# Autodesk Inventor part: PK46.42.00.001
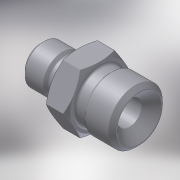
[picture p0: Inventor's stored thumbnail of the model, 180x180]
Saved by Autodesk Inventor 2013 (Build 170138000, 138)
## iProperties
Created: 2005-06
Part Number: PK46.42.00.001
Material: Steel, Mild
Document SubType Name: Modeling
Designer: salex
Manufacturer: Standard
Standards Organization: Custom
Density: 7.86 g/cm^3
Mass: 73.9851 g
Surface Area: 45.5262 cm^2
Volume: 9.41287 cm^3
Author: salex
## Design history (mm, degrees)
sketch "Эскиз1"
  geometry: L1 (0, 0)-(44.165, 0); L2 (0, 5)-(0, 8); L3 (0, 8)-(8.9, 8); L4 (8.9, 8)-(10, 6.9); L5 (10, 6.9)-(14, 6.9); L6 (14, 6.9)-(14, 8); L7 (14, 8)-(15, 8); L8 (15, 8)-(15, 12); L9 (15, 12)-(16.732, 15); L10 (16.732, 15)-(22.268, 15); L11 (22.268, 15)-(24, 12); L12 (24, 12)-(24, 9.9); L13 (24, 9.9)-(28, 9.9); L14 (28, 9.9)-(29.1, 11); L15 (29.1, 11)-(40, 11); L16 (40, 11)-(40, 9); L17 (40, 9)-(36, 5); L18 (36, 5)-(0, 5)
  constraints: 36 end point, 9 parallel, 2 perpendicular, 1 collinear, 1 equal length, 1 horizontal, 1 other
  dimensions: "d0" = 0 distance from line of L1.start L2; "d1" = 15 distance between parallel lines of L8 L2; "d2" = 40 distance between parallel lines of L16 L2; "d3" = 16 distance between parallel lines of L16 L12; "d4" = 30 diameter of L10 L1; "d5" = 10 diameter of L18 L1; "d6" = 45 deg angle of L18 L17; "d7" = 18 diameter of L16.end L1; "d8" = 22 diameter of L15 L1; "d9" = 19.8 diameter of L13 L1; "d10" = 45 deg angle of L14 L13; "d11" = 4 distance of L12.end L13.end; "d12" = 16 diameter of L3 L1; "d13" = 13.8 diameter of L5 L1; "d14" = 4 distance of L4.end L5.end; "d15" = 1 distance of L6.end L7.end; "d16" = 16 diameter of L7 L1; "d17" = 45 deg angle of L5 L4; "d18" = 24 diameter of L8.end L1; "d19" = 0 vertical distance of L8.end L11.end; "d20" = 30 deg angle of L8 L9
revolve "Вращение1" sketch "Эскиз1" stored, may be unused: angle "d21" = 90 deg
chamfer "Фаска1" distance "d22" = 1.6; stored, may be unused: second distance "d23" = 2, angle "d24" = 45 deg
fillet "Сопряжение1" dims "d25" = 1
fillet "Сопряжение2" dims "d26" = 0.5
sketch "Эскиз2"
  geometry: L1 (0, 13.856)-(12, 6.928); L2 (12, 6.928)-(12, -6.928); L3 (12, -6.928)-(0, -13.856); L4 (0, -13.856)-(-12, -6.928); L5 (-12, -6.928)-(-12, 6.928); L6 (-12, 6.928)-(0, 13.856); C1 r 6.4 at (0, 0) reference; 1 further point
  constraints: 12 end point, 1 coincident, 11 other
  dimensions: "d27" = 24 distance between parallel lines of L2 L5
extrude "Выдавливание1" sketch "Эскиз2" stored distance "d28" = 10; taper "d29" = 0 deg
body "Solid1"
